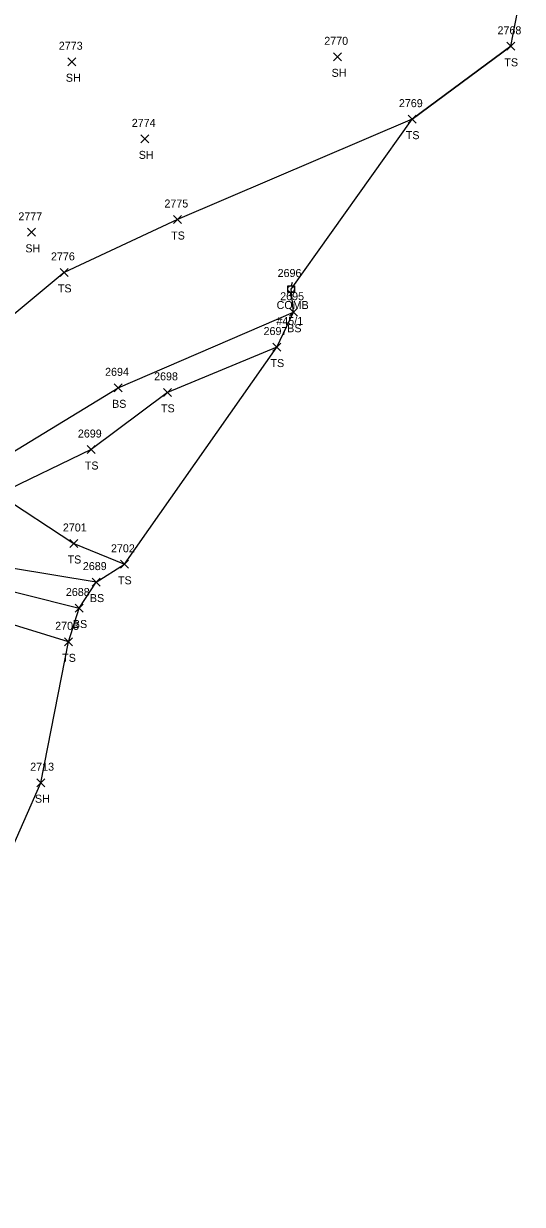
# Model space of a CAD drawing. Extents: x 1633660 to 1636532, y 388643 to 392631.
# Drawn here: x 1634910.5 to 1635035.1, y 389113.6 to 389408.7 of the extents above; entities that cross this region are included whole.
import ezdxf

# ---------------------------------------------------------------- set-up
doc = ezdxf.new("R2010")
doc.units = 0
for name, color, linetype in [('L_A', 7, 'Continuous'), ('L_I', 7, 'Continuous'), ('L_TIC', 7, 'Continuous'), ('LELB', 7, 'Continuous'), ('LSOGP', 7, 'Continuous'), ('U_A', 7, 'Continuous'), ('U_C', 7, 'Continuous'), ('U_I', 7, 'Continuous'), ('UP', 7, 'Continuous')]:
    doc.layers.add(name, color=color, linetype=linetype)

msp = doc.modelspace()

# ---------------------------------------------------------------- linework, layer by layer
at = {"layer": 'L_TIC'}
for points in [[(1635031.21, 389402.07), (1635033.21, 389404.07)], [(1635033.21, 389402.07), (1635031.21, 389404.07)], [(1634987.97, 389399.44), (1634989.97, 389401.44)], [(1634989.97, 389399.44), (1634987.97, 389401.44)], [(1634921.58, 389398.21), (1634923.58, 389400.21)], [(1634923.58, 389398.21), (1634921.58, 389400.21)], [(1635006.58, 389383.86), (1635008.58, 389385.86)], [(1635008.58, 389383.86), (1635006.58, 389385.86)], [(1634939.8, 389378.93), (1634941.8, 389380.93)], [(1634941.8, 389378.93), (1634939.8, 389380.93)], [(1634947.96, 389358.77), (1634949.96, 389360.77)], [(1634949.96, 389358.77), (1634947.96, 389360.77)], [(1634911.47, 389355.57), (1634913.47, 389357.57)], [(1634913.47, 389355.57), (1634911.47, 389357.57)], [(1634919.67, 389345.56), (1634921.67, 389347.56)], [(1634921.67, 389345.56), (1634919.67, 389347.56)], [(1634976.92, 389335.59), (1634978.92, 389337.59)], [(1634978.92, 389335.59), (1634976.92, 389337.59)], [(1634972.77, 389326.89), (1634974.77, 389328.89)], [(1634974.77, 389326.89), (1634972.77, 389328.89)], [(1634933.18, 389316.7), (1634935.18, 389318.7)], [(1634935.18, 389316.7), (1634933.18, 389318.7)], [(1634945.43, 389315.57), (1634947.43, 389317.57)], [(1634947.43, 389315.57), (1634945.43, 389317.57)], [(1634926.4, 389301.27), (1634928.4, 389303.27)], [(1634928.4, 389301.27), (1634926.4, 389303.27)], [(1634922.1, 389277.79), (1634924.1, 389279.79)], [(1634924.1, 389277.79), (1634922.1, 389279.79)], [(1634934.69, 389272.59), (1634936.69, 389274.59)], [(1634936.69, 389272.59), (1634934.69, 389274.59)], [(1634927.63, 389268.14), (1634929.63, 389270.14)], [(1634929.63, 389268.14), (1634927.63, 389270.14)], [(1634923.39, 389261.66), (1634925.39, 389263.66)], [(1634925.39, 389261.66), (1634923.39, 389263.66)], [(1634920.74, 389253.21), (1634922.74, 389255.21)], [(1634922.74, 389253.21), (1634920.74, 389255.21)], [(1634913.86, 389217.99), (1634915.86, 389219.99)], [(1634915.86, 389217.99), (1634913.86, 389219.99)]]:
    msp.add_lwpolyline(points, dxfattribs=at)
at = {"layer": 'LELB'}
for points in [[(1635032.21, 389403.07), (1635007.58, 389384.86), (1634948.96, 389359.77), (1634920.67, 389346.56), (1634889.07, 389320.29), (1634868.06, 389304.45)], [(1634928.63, 389269.14), (1634907.52, 389272.61), (1634904.9, 389276.76), (1634895.25, 389290.67), (1634903.72, 389299.19), (1634934.18, 389317.7), (1634977.92, 389336.59)], [(1634973.77, 389327.89), (1634946.43, 389316.57), (1634927.4, 389302.27), (1634904.24, 389291.08), (1634923.1, 389278.79), (1634935.69, 389273.59)], [(1634885.2, 389186.65), (1634878.4, 389201.57), (1634873.97, 389215.97), (1634863.77, 389240.55), (1634858.4, 389257.47), (1634859.3, 389264.69), (1634887.19, 389287.34), (1634897.16, 389277.97), (1634895.84, 389269.83), (1634924.39, 389262.66)], [(1634921.74, 389254.21), (1634891.18, 389263.6), (1634890.3, 389276.32), (1634879.4, 389266.85), (1634868.16, 389256.66)]]:
    msp.add_lwpolyline(points, dxfattribs=at)
at = {"layer": 'LSOGP'}
msp.add_lwpolyline([(1634849.33, 389112.53), (1634851.42, 389137.05), (1634872.35, 389171.96), (1634882.02, 389178.69), (1634885.2, 389186.65), (1634891.47, 389190.38), (1634906.31, 389199.61), (1634914.86, 389218.99), (1634921.74, 389254.21), (1634924.39, 389262.66), (1634928.63, 389269.14), (1634935.69, 389273.59), (1634973.77, 389327.89), (1634977.92, 389336.59), (1634977.33, 389342.4), (1635007.58, 389384.86), (1635032.21, 389403.07), (1635035.11, 389418.19)], dxfattribs=at)
at = {"layer": 'UP'}
for p, q in [((1634976.5, 389341.57), (1634976.5, 389343.23)), ((1634976.5, 389343.23), (1634978.16, 389343.23)), ((1634978.16, 389341.57), (1634976.5, 389341.57)), ((1634977.08, 389340.73), (1634977.33, 389341.57)), ((1634977.58, 389344.07), (1634977.33, 389343.23)), ((1634977.33, 389342.4), (1634977.33, 389342.4)), ((1634978.16, 389343.23), (1634978.16, 389341.57))]:
    msp.add_line(p, q, dxfattribs=at)
msp.add_circle((1634977.33, 389342.4), 0.833, dxfattribs=at)

# ---------------------------------------------------------------- texts
at = {"layer": 'L_A'}
for s, p in [('SH', (1634987.46, 389395.44)), ('TS', (1635030.62, 389398.07)), ('SH', (1634921.07, 389394.21)), ('TS', (1635005.99, 389379.86)), ('SH', (1634939.29, 389374.93)), ('TS', (1634947.37, 389354.77)), ('SH', (1634910.96, 389351.57)), ('TS', (1634919.08, 389341.56)), ('BS', (1634976.37, 389331.59)), ('TS', (1634972.18, 389322.89)), ('BS', (1634932.62, 389312.7)), ('TS', (1634944.84, 389311.57)), ('TS', (1634925.81, 389297.27)), ('TS', (1634921.51, 389273.79)), ('TS', (1634934.1, 389268.59)), ('BS', (1634927.07, 389264.14)), ('BS', (1634922.83, 389257.66)), ('TS', (1634920.15, 389249.21)), ('SH', (1634913.35, 389213.99))]:
    msp.add_text(s, height=2, dxfattribs=at).set_placement(p)
at = {"layer": 'L_I'}
for s, p in [('2768', (1635028.9, 389406.07)), ('2773', (1634919.32, 389402.21)), ('2770', (1634985.63, 389403.44)), ('2769', (1635004.27, 389387.86)), ('2774', (1634937.54, 389382.93)), ('2775', (1634945.7, 389362.77)), ('2777', (1634909.21, 389359.57)), ('2776', (1634917.36, 389349.56)), ('2695', (1634974.62, 389339.59)), ('2697', (1634970.46, 389330.89)), ('2694', (1634930.87, 389320.7)), ('2698', (1634943.12, 389319.57)), ('2699', (1634924.08, 389305.27)), ('2701', (1634920.33, 389281.79)), ('2702', (1634932.35, 389276.59)), ('2689', (1634925.32, 389272.14)), ('2688', (1634921.08, 389265.66)), ('2703', (1634918.41, 389257.21)), ('2713', (1634912.17, 389221.99))]:
    msp.add_text(s, height=2, dxfattribs=at).set_placement(p)
at = {"layer": 'U_A'}
msp.add_text('COMB', height=2, dxfattribs=at).set_placement((1634973.72, 389337.4))
at = {"layer": 'U_C'}
msp.add_text('#45/1', height=2, dxfattribs=at).set_placement((1634973.66, 389333.4))
at = {"layer": 'U_I'}
msp.add_text('2696', height=2, dxfattribs=at).set_placement((1634973.97, 389345.4))

doc.saveas('drawing.dxf')
